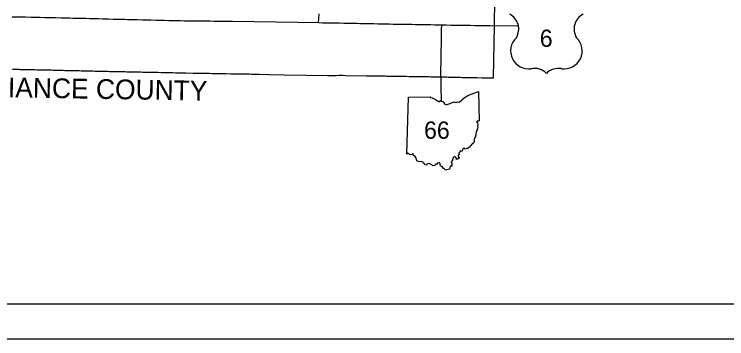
# Model space of a CAD drawing. Extents: x -66 to 795, y 0 to 440.
# Drawn here: x 383.6 to 589.3, y 0 to 93.6 of the extents above; entities that cross this region are included whole.
import ezdxf

# ---------------------------------------------------------------- set-up
doc = ezdxf.new("R2010")
doc.units = 0
for name, color, linetype in [('GM_X_Adjacent_County_Text', 7, 'Continuous'), ('GM_X_County', 7, 'Continuous'), ('GM_X_State_Route', 7, 'Continuous'), ('GM_X_US_Route', 7, 'Continuous'), ('PV_P_Text', 7, 'Continuous'), ('SH_Border', 7, 'Continuous'), ('SH_Cut_Line', 7, 'Continuous')]:
    doc.layers.add(name, color=color, linetype=linetype)

msp = doc.modelspace()

# ---------------------------------------------------------------- linework, layer by layer
at = {"layer": 'GM_X_County'}
msp.add_lwpolyline([(383.13, 77.77), (383.85, 77.76), (384.73, 77.73), (384.97, 77.73), (385.18, 77.72), (385.54, 77.72), (385.89, 77.71), (386.08, 77.7), (387.03, 77.68), (387.61, 77.67), (388.22, 77.66), (388.82, 77.65), (389.57, 77.63), (390.21, 77.61), (390.57, 77.61), (390.89, 77.6), (391.48, 77.59), (391.91, 77.58), (392.23, 77.57), (392.86, 77.55), (393.62, 77.54), (394.06, 77.53), (394.38, 77.53), (394.86, 77.51), (395.48, 77.5), (395.81, 77.49), (396.58, 77.47), (397.68, 77.44), (398.16, 77.43), (399.34, 77.4), (399.77, 77.4), (400.05, 77.39), (400.1, 77.39), (400.49, 77.38), (400.64, 77.37), (401.19, 77.36), (401.8, 77.35), (402.39, 77.34), (402.96, 77.33), (403.79, 77.3), (404.31, 77.3), (404.76, 77.29), (404.94, 77.28), (405.2, 77.28), (405.5, 77.27), (405.79, 77.27), (406.31, 77.25), (406.83, 77.24), (407.36, 77.23), (407.92, 77.21), (408.26, 77.21), (408.44, 77.2), (409, 77.19), (409.38, 77.18), (409.84, 77.17), (410.16, 77.16), (410.62, 77.16), (411.13, 77.14), (411.58, 77.13), (412.06, 77.13), (412.28, 77.12), (412.95, 77.11), (413.43, 77.09), (414.05, 77.08), (414.61, 77.06), (414.81, 77.06), (415.15, 77.05), (415.55, 77.05), (416.12, 77.03), (416.73, 77.02), (417.13, 77.02), (417.89, 77), (418.74, 76.99), (419.09, 76.98), (420.18, 76.96), (420.7, 76.95), (421.06, 76.94), (421.5, 76.93), (421.75, 76.92), (422.84, 76.9), (423.23, 76.9), (424.09, 76.88), (424.53, 76.87), (425.06, 76.86), (426.03, 76.84), (426.44, 76.83), (426.59, 76.83), (427.19, 76.82), (428.1, 76.8), (428.5, 76.8), (428.97, 76.79), (429.37, 76.78), (430.14, 76.76), (430.21, 76.76), (433.13, 76.7), (435.26, 76.66), (436.83, 76.63), (437.21, 76.62), (437.91, 76.61), (438.64, 76.59), (439.41, 76.58), (439.99, 76.57), (440.71, 76.56), (441.55, 76.55), (442.36, 76.53), (443.82, 76.51), (444.65, 76.5), (446.18, 76.47), (446.4, 76.46), (447.15, 76.45), (447.92, 76.44), (448.29, 76.43), (449.26, 76.41), (450.08, 76.4), (450.82, 76.39), (451.57, 76.38), (452.1, 76.37), (452.74, 76.36), (453.33, 76.35), (453.78, 76.35), (453.9, 76.34), (453.95, 76.34), (453.99, 76.33), (454.05, 76.31), (454.07, 76.32), (454.08, 76.33), (454.09, 76.33), (454.09, 76.33), (454.12, 76.33), (454.19, 76.33), (454.29, 76.33), (457.1, 76.26), (461.52, 76.18), (474.05, 75.95), (474.09, 75.95), (474.13, 75.96), (474.18, 75.96), (474.23, 75.96), (474.5, 75.97), (475.01, 75.97), (476.47, 75.99), (477.42, 76), (477.73, 76.01), (478.14, 76.01), (478.32, 76), (478.48, 76), (479.25, 75.99), (485.35, 75.86), (485.5, 75.86), (485.64, 75.86), (485.79, 75.86), (485.97, 75.86), (486.27, 75.87), (487.49, 75.85), (488, 75.84), (488.68, 75.83), (489.07, 75.82), (489.8, 75.81), (490.49, 75.8), (490.82, 75.8), (491.15, 75.79), (491.51, 75.79), (491.66, 75.79), (491.71, 75.79), (491.76, 75.79), (492.41, 75.78), (492.85, 75.78), (493.35, 75.77), (493.96, 75.76), (495.08, 75.74), (496.16, 75.72), (496.72, 75.72), (497.61, 75.7), (498.96, 75.68), (499.61, 75.67), (500.67, 75.65), (501.45, 75.64), (502.26, 75.63), (503.09, 75.61), (503.5, 75.61), (503.99, 75.6), (504.62, 75.59), (505.34, 75.57), (505.96, 75.56), (506.31, 75.55), (506.71, 75.55), (506.82, 75.55), (507.16, 75.54), (507.59, 75.53), (508.42, 75.51), (508.86, 75.5), (509.43, 75.49), (509.97, 75.47), (510.53, 75.46), (511.12, 75.45), (511.81, 75.43), (512.33, 75.42), (512.87, 75.41), (514.19, 75.38), (514.78, 75.37), (515.28, 75.36), (515.71, 75.35), (517.13, 75.32), (518.62, 75.29), (519.87, 75.27), (521.18, 75.24), (521.89, 75.23), (521.95, 75.23), (522.24, 90.34), (522.47, 105.46)], dxfattribs=at)
at = {"layer": 'GM_X_State_Route'}
for points in [[(471.46, 91.21), (471.53, 92.35), (471.63, 93.75)], [(506.95, 68.36), (506.78, 77.69), (506.82, 79.74), (506.86, 81.54), (506.89, 83.29), (506.92, 84.82), (506.95, 86.3), (506.97, 87.39), (507, 89.1), (507.03, 90.56)]]:
    msp.add_lwpolyline(points, dxfattribs=at)
at = {"layer": 'GM_X_US_Route'}
for points in [[(383.03, 92.91), (384.28, 92.89), (385.24, 92.87), (386.88, 92.84), (388.48, 92.8), (389.88, 92.76), (391.06, 92.75), (392.46, 92.71), (394.02, 92.68), (395.47, 92.64), (397.15, 92.61), (398.49, 92.57), (399.61, 92.54), (400.52, 92.53), (401.76, 92.5), (403.09, 92.47), (404.29, 92.45), (405.43, 92.43), (406.55, 92.4), (407.87, 92.37), (409.14, 92.33), (410.82, 92.29), (412.13, 92.23), (413.49, 92.21), (414.96, 92.18), (415.52, 92.17), (416.32, 92.14), (417.67, 92.11), (419.1, 92.07), (420.61, 92.03), (421.82, 92), (421.83, 92), (423.06, 91.96), (424.56, 91.93), (425.92, 91.89), (426.73, 91.87), (427.03, 91.87), (428.24, 91.84), (429.51, 91.81), (430.53, 91.79), (431.59, 91.77), (432.8, 91.76), (433.91, 91.74), (435.3, 91.73), (436.78, 91.71), (438, 91.69), (439.05, 91.68), (440.07, 91.67), (441.21, 91.65), (442.39, 91.64), (443.73, 91.62), (444.87, 91.6), (445.82, 91.59), (446.65, 91.58), (465.48, 91.3)], [(465.48, 91.3), (471.46, 91.21), (472.58, 91.18), (473.87, 91.16), (474.93, 91.14), (475.61, 91.12), (475.98, 91.12), (477.42, 91.09), (478.72, 91.06), (479.89, 91.04), (480.99, 91.02), (482.21, 91.01), (482.59, 91), (483.35, 90.97), (484.71, 90.95), (486.13, 90.92), (487.39, 90.9), (488.7, 90.88), (489.79, 90.86), (490.94, 90.81), (491.99, 90.82), (493.05, 90.8), (494.21, 90.79), (495.41, 90.77), (496.18, 90.76), (497.32, 90.73), (498.4, 90.71), (499.34, 90.68), (500.58, 90.67), (501.69, 90.65), (502.87, 90.63), (503.91, 90.61), (504.97, 90.59), (506.04, 90.57), (507.03, 90.56), (508.27, 90.53), (509.65, 90.51), (510.83, 90.5), (512.11, 90.48), (513.11, 90.46), (514.21, 90.45), (515.36, 90.43), (516.62, 90.41), (517.72, 90.39), (518.87, 90.39), (519.92, 90.37), (521, 90.35), (529.33, 90.31)]]:
    msp.add_lwpolyline(points, dxfattribs=at)
at = {"layer": 'PV_P_Text'}
msp.add_line((496.94, 53.28), (497.4, 69.65), dxfattribs=at)
msp.add_line((496.94, 53.28), (497.4, 69.65), dxfattribs=at)
for points in [[(497.4, 69.65), (503.75, 69.76), (503.65, 69.56), (504.25, 69.52), (504.89, 69.17), (505.43, 68.95), (506.08, 68.43), (506.48, 68.43), (506.64, 68.86), (506.95, 68.53), (507.3, 68.47), (507.92, 67.69), (508.44, 67.52), (509.05, 67.79), (509.51, 67.83), (509.84, 68.1), (510.71, 68.32), (510.95, 68.19), (511.42, 68.21), (511.65, 68.31), (512.05, 68.22), (512.76, 68.82), (513.49, 69.52), (514.61, 70.18), (516.29, 70.81), (517.61, 71.37), (517.8, 62.88)], [(497.4, 69.65), (503.75, 69.76), (503.65, 69.56), (504.25, 69.52), (504.89, 69.17), (505.43, 68.95), (506.08, 68.43), (506.48, 68.43), (506.64, 68.86), (506.95, 68.53), (507.3, 68.47), (507.92, 67.69), (508.44, 67.52), (509.05, 67.79), (509.51, 67.83), (509.84, 68.1), (510.71, 68.32), (510.95, 68.19), (511.42, 68.21), (511.65, 68.31), (512.05, 68.22), (512.76, 68.82), (513.49, 69.52), (514.61, 70.18), (516.29, 70.81), (517.61, 71.37), (517.8, 62.88)], [(517.8, 62.88), (517.61, 62.76), (517.3, 62.81), (517.1, 62.57), (517.35, 62.18), (517.47, 61.76), (517.37, 61.29), (517.47, 60.91), (517.4, 60.59), (517.21, 60.27), (517.14, 59.97), (516.98, 59.65), (516.99, 59.47), (516.84, 59.33), (516.87, 58.8), (516.79, 58.51), (516.81, 58.25), (516.56, 58.18), (516.62, 57.97), (516.46, 57.81), (516.49, 57.53), (516.31, 57.36), (516.49, 57), (516.35, 56.89), (516.23, 56.45), (515.91, 56.36), (515.26, 55.57), (515.03, 55.27), (514.78, 55.2), (514.64, 54.89), (514.32, 54.89), (513.84, 54.67), (513.54, 55.04), (513, 54.6), (512.93, 54.09), (512.25, 54.11), (512.28, 53.85), (512.12, 53.77), (511.98, 53.51), (512.07, 53.05), (511.75, 52.94), (511.78, 52.67), (511.99, 52.51), (512.08, 52), (511.74, 52.1), (511.46, 51.67), (511.18, 51.77), (511.27, 52.14), (510.78, 52.57), (510.33, 52.22), (510.09, 51.66), (510.09, 51.29), (509.74, 51.06), (509.96, 50.53), (509.92, 50.16), (509.93, 49.81), (509.5, 49.82), (509.24, 48.88)], [(517.8, 62.88), (517.61, 62.76), (517.3, 62.81), (517.1, 62.57), (517.35, 62.18), (517.47, 61.76), (517.37, 61.29), (517.47, 60.91), (517.4, 60.59), (517.21, 60.27), (517.14, 59.97), (516.98, 59.65), (516.99, 59.47), (516.84, 59.33), (516.87, 58.8), (516.79, 58.51), (516.81, 58.25), (516.56, 58.18), (516.62, 57.97), (516.46, 57.81), (516.49, 57.53), (516.31, 57.36), (516.49, 57), (516.35, 56.89), (516.23, 56.45), (515.91, 56.36), (515.26, 55.57), (515.03, 55.27), (514.78, 55.2), (514.64, 54.89), (514.32, 54.89), (513.84, 54.67), (513.54, 55.04), (513, 54.6), (512.93, 54.09), (512.25, 54.11), (512.28, 53.85), (512.12, 53.77), (511.98, 53.51), (512.07, 53.05), (511.75, 52.94), (511.78, 52.67), (511.99, 52.51), (512.08, 52), (511.74, 52.1), (511.46, 51.67), (511.18, 51.77), (511.27, 52.14), (510.78, 52.57), (510.33, 52.22), (510.09, 51.66), (510.09, 51.29), (509.74, 51.06), (509.96, 50.53), (509.92, 50.16), (509.93, 49.81), (509.5, 49.82), (509.24, 48.88)], [(509.24, 48.88), (508.5, 48.7), (507.99, 48.6), (507.81, 49.02), (507.44, 49.25), (507.2, 49.68), (506.67, 49.74), (506.55, 50.33), (506.49, 50.81), (505.76, 50.69), (505.57, 50.39), (505.31, 50.32), (505.16, 50.02), (504.81, 50), (504.44, 49.86), (504.19, 50.15), (503.58, 50.44), (503.3, 50.59), (502.72, 50.35), (502.6, 50.08), (502.14, 50.2), (502.03, 50.51), (501.76, 50.6), (501.69, 50.93), (501.1, 51.1), (500.65, 51.03), (499.84, 51.29), (499.79, 51.72), (499.52, 52.24), (499.38, 52.61), (498.87, 52.88), (498.77, 53.32), (498.61, 53.3), (498.46, 53.13), (497.9, 53.05), (497.67, 53.22), (497.36, 53.53), (496.94, 53.28)], [(509.24, 48.88), (508.5, 48.7), (507.99, 48.6), (507.81, 49.02), (507.44, 49.25), (507.2, 49.68), (506.67, 49.74), (506.55, 50.33), (506.49, 50.81), (505.76, 50.69), (505.57, 50.39), (505.31, 50.32), (505.16, 50.02), (504.81, 50), (504.44, 49.86), (504.19, 50.15), (503.58, 50.44), (503.3, 50.59), (502.72, 50.35), (502.6, 50.08), (502.14, 50.2), (502.03, 50.51), (501.76, 50.6), (501.69, 50.93), (501.1, 51.1), (500.65, 51.03), (499.84, 51.29), (499.79, 51.72), (499.52, 52.24), (499.38, 52.61), (498.87, 52.88), (498.77, 53.32), (498.61, 53.3), (498.46, 53.13), (497.9, 53.05), (497.67, 53.22), (497.36, 53.53), (496.94, 53.28)]]:
    msp.add_lwpolyline(points, dxfattribs=at)
for centre, radius, start, end in [((524.44, 89.33), 4.82, 329.1175, 62.6108), ((524.44, 89.33), 4.82, 329.1175, 62.6108), ((550.06, 89.33), 4.82, 117.3892, 210.8825), ((550.06, 89.33), 4.82, 117.3892, 210.8825), ((532.12, 83.05), 5.2, 133.0046, 278.7282), ((532.12, 83.05), 5.2, 133.0046, 278.7282), ((542.38, 83.05), 5.2, 261.2718, 46.9954), ((542.38, 83.05), 5.2, 261.2718, 46.9954), ((533.87, 73.36), 4.65, 43.4177, 101.8742), ((533.87, 73.36), 4.65, 43.4177, 101.8742), ((540.73, 73.05), 4.94, 79.9613, 134.7468), ((540.73, 73.05), 4.94, 79.9613, 134.7468)]:
    msp.add_arc(centre, radius, start, end, dxfattribs=at)
at = {"layer": 'SH_Border'}
msp.add_lwpolyline([(30, 430), (670, 430), (670, 10), (30, 10)], close=True, dxfattribs=at)
at = {"layer": 'SH_Cut_Line'}
msp.add_lwpolyline([(0, 0), (680, 0), (680, 440), (0, 440)], close=True, dxfattribs=at)

# ---------------------------------------------------------------- texts
at = {"layer": 'GM_X_Adjacent_County_Text'}
msp.add_text('DEFIANCE COUNTY', height=5.7, rotation=359.0284, dxfattribs=at).set_placement((366.5, 69.92))
at = {"layer": 'PV_P_Text'}
for s, height, p in [('6', 4.99, (535.33, 84.19)), ('66', 4.987, (501.92, 57.68))]:
    msp.add_text(s, height=height, dxfattribs=at).set_placement(p)

doc.saveas('drawing.dxf')
